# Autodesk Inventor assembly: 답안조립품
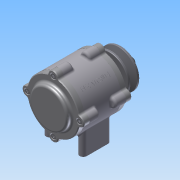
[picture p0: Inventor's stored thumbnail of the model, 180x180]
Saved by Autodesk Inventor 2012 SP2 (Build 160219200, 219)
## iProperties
Created: 2015-03
Part Number: 답안조립품
Document SubType Name: Assembly
Designer: Administrator
Author: Administrator
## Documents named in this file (11)
- C:\Users\Administrator\Desktop\450306V1028\답안조립품.iam
- C:\Users\Administrator\Desktop\450306V1028\본체.ipt
- C:\Users\Administrator\Desktop\450306V1028\축.ipt
- C:\Users\Administrator\Desktop\450306V1028\V벨트풀리.ipt
- C:\Users\Administrator\Desktop\450306V1028\커버.ipt
- C:\Users\Administrator\Desktop\450306V1028\커버2.ipt
- C:\Users\Administrator\Desktop\450306V1028\베어링 6204.ipt
- C:\Users\Administrator\Desktop\450306V1028\오일실.ipt
- C:\Users\Administrator\Desktop\450306V1028\키(4 x 4 x 12).ipt
- C:\Users\Administrator\Desktop\450306V1028\너트 M12x1.25.ipt
- C:\Users\Administrator\Desktop\450306V1028\M 4 x 12.ipt
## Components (14 placed, 6 different names)
1. 그루브 풀리1:1
2. KS B 2023 6204 - 20 x 47 x 14:1
3. KS B 2023 6204 - 20 x 47 x 14:2
4. KS B 2804 D D - 20 32 8:1
5. KS B 1311 (I) 4 x 4 x 12:1
6. KS B 1012 클래스 1 일반 - 미터 M12x1.25:1
7. KS B 1003 - 미터 M 4 x 12:1
8. KS B 1003 - 미터 M 4 x 12:2
9. KS B 1003 - 미터 M 4 x 12:3
10. KS B 1003 - 미터 M 4 x 12:4
11. KS B 1003 - 미터 M 4 x 12:5
12. KS B 1003 - 미터 M 4 x 12:6
13. KS B 1003 - 미터 M 4 x 12:7
14. KS B 1003 - 미터 M 4 x 12:8
